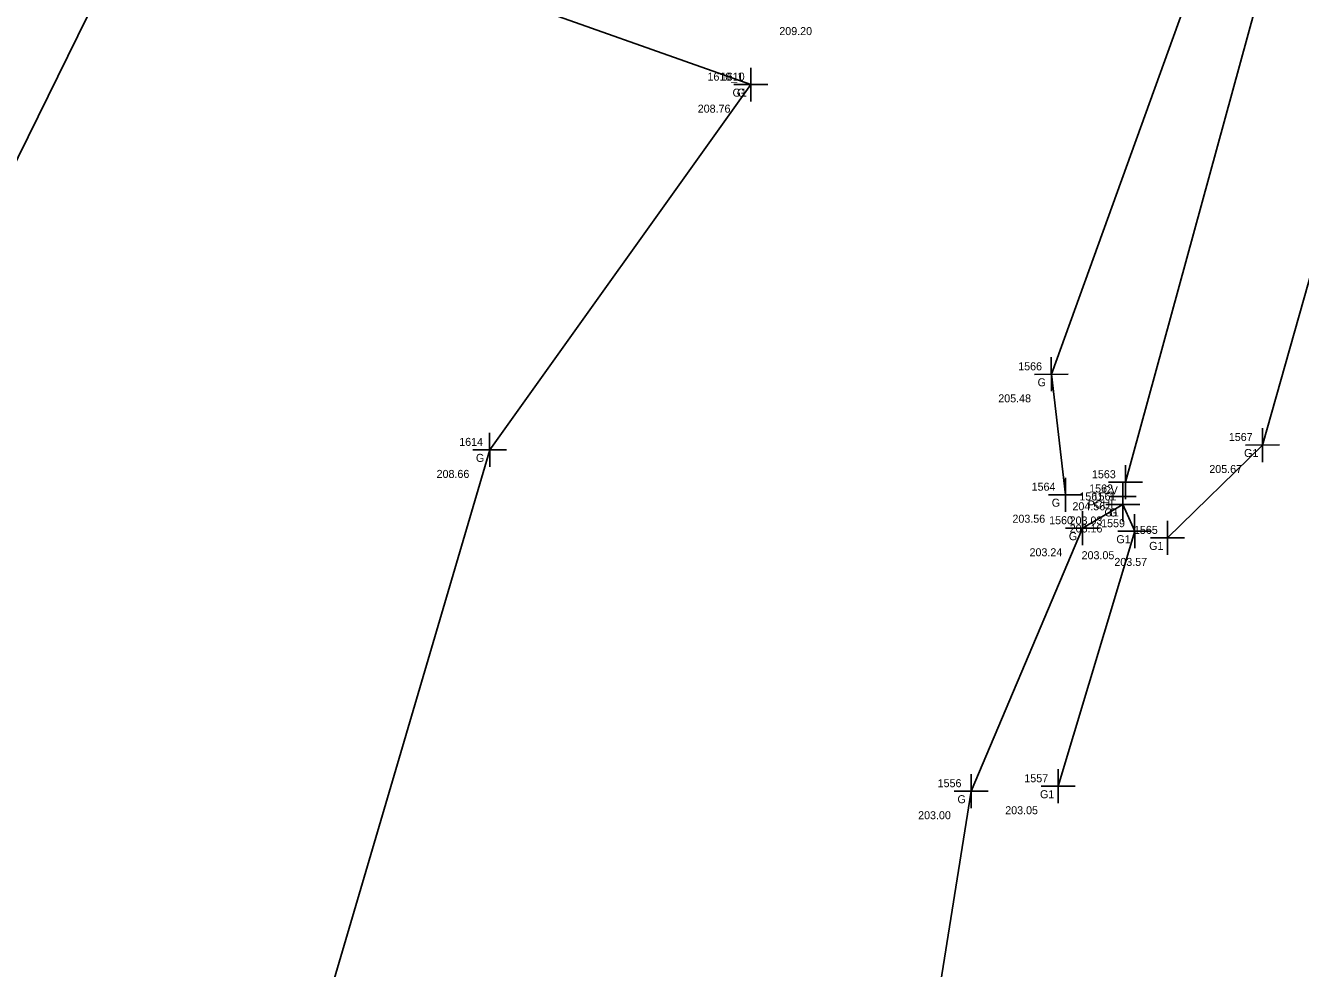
# Model space of a CAD drawing. Extents: x 1158983 to 1160032, y 610902 to 611573.
# Drawn here: x 1159316.41 to 1159364.21, y 611195.03 to 611230.37 of the extents above; entities that cross this region are included whole.
import ezdxf

# ---------------------------------------------------------------- set-up
doc = ezdxf.new("R2010")
doc.units = 0
for name, color, linetype in [('Default', 7, 'Continuous'), ('S_Drainage_Culvert_Top', 7, 'Continuous'), ('S_Drainage_Invert', 7, 'Continuous'), ('S_Field_Code', 7, 'Continuous'), ('S_Ground_Elevation', 7, 'Continuous'), ('S_Point_Elevation', 7, 'Continuous'), ('S_Point_Name', 7, 'Continuous'), ('S_Survey_Shot', 7, 'Continuous')]:
    doc.layers.add(name, color=color, linetype=linetype)

msp = doc.modelspace()

# ---------------------------------------------------------------- linework, layer by layer
at = {"layer": 'Default'}
msp.add_line((1159357.543, 611212.718), (1159357.543, 611212.718), dxfattribs=at)
at = {"layer": 'S_Drainage_Culvert_Top'}
msp.add_lwpolyline([(1159357.648, 611213.251), (1159368.247, 611251.957)], dxfattribs=at)
at = {"layer": 'S_Drainage_Invert'}
for p, q in [((1159357.543, 611213.218), (1159357.543, 611212.218)), ((1159357.043, 611212.718), (1159358.043, 611212.718))]:
    msp.add_line(p, q, dxfattribs=at)
at = {"layer": 'S_Ground_Elevation'}
for points in [[(1159355.399, 611212.784), (1159354.868, 611217.296), (1159362.619, 611238.747), (1159363.344, 611248.476), (1159364.893, 611252.092), (1159367.286, 611253.012), (1159367.04, 611258.265), (1159369.176, 611279.512)], [(1159359.22, 611211.166), (1159362.779, 611214.646), (1159369.471, 611238.288), (1159371.639, 611247.54), (1159371.624, 611251.498), (1159369.477, 611252.693), (1159372.225, 611257.365), (1159373.898, 611277.257)], [(1159343.602, 611228.151), (1159333.924, 611231.59), (1159320.612, 611234.544), (1159314.265, 611221.651), (1159310.207, 611192.625), (1159301.313, 611165.491), (1159294.216, 611125.97), (1159281.365, 611085.012)], [(1159343.602, 611228.151), (1159333.813, 611214.463), (1159327.549, 611193.141), (1159320.093, 611162.672), (1159311.847, 611125.314), (1159302.792, 611085.335), (1159282.623, 611040.075), (1159275.499, 611004.928), (1159281.6, 610988.313)], [(1159311.353, 611030.991), (1159320.755, 611050.625), (1159326.586, 611072.012), (1159334.597, 611111.75), (1159339.581, 611147.922), (1159349.474, 611186.733), (1159351.864, 611201.672), (1159356.04, 611211.527), (1159357.544, 611212.419)], [(1159355.129, 611201.859), (1159357.992, 611211.416), (1159357.544, 611212.419)]]:
    msp.add_lwpolyline(points, dxfattribs=at)
at = {"layer": 'S_Survey_Shot'}
for p, q in [((1159343.603, 611227.515), (1159343.601, 611228.787)), ((1159343.603, 611227.515), (1159343.601, 611228.787)), ((1159342.966, 611228.15), (1159344.238, 611228.152)), ((1159342.966, 611228.15), (1159344.238, 611228.152)), ((1159343.602, 611228.151), (1159343.602, 611228.151)), ((1159343.602, 611228.151), (1159343.602, 611228.151)), ((1159354.869, 611216.659), (1159354.867, 611217.932)), ((1159354.232, 611217.294), (1159355.504, 611217.297)), ((1159354.868, 611217.296), (1159354.868, 611217.296)), ((1159333.814, 611213.826), (1159333.811, 611215.099)), ((1159362.781, 611214.009), (1159362.778, 611215.282)), ((1159362.143, 611214.644), (1159363.416, 611214.647)), ((1159362.779, 611214.646), (1159362.779, 611214.646)), ((1159333.177, 611214.461), (1159334.449, 611214.464)), ((1159333.813, 611214.463), (1159333.813, 611214.463)), ((1159357.649, 611212.615), (1159357.647, 611213.887)), ((1159355.401, 611212.147), (1159355.398, 611213.42)), ((1159357.012, 611213.25), (1159358.284, 611213.252)), ((1159357.648, 611213.251), (1159357.648, 611213.251)), ((1159354.763, 611212.782), (1159356.036, 611212.785)), ((1159355.399, 611212.784), (1159355.399, 611212.784)), ((1159357.545, 611211.783), (1159357.542, 611213.056)), ((1159357.545, 611211.783), (1159357.542, 611213.056)), ((1159356.907, 611212.418), (1159358.18, 611212.421)), ((1159356.907, 611212.418), (1159358.18, 611212.421)), ((1159357.544, 611212.419), (1159357.544, 611212.419)), ((1159357.544, 611212.419), (1159357.544, 611212.419)), ((1159356.041, 611210.891), (1159356.039, 611212.163)), ((1159357.994, 611210.78), (1159357.991, 611212.053)), ((1159359.222, 611210.529), (1159359.219, 611211.802)), ((1159355.404, 611211.526), (1159356.676, 611211.528)), ((1159356.04, 611211.527), (1159356.04, 611211.527)), ((1159357.356, 611211.415), (1159358.628, 611211.418)), ((1159357.992, 611211.416), (1159357.992, 611211.416)), ((1159358.584, 611211.164), (1159359.857, 611211.167)), ((1159359.22, 611211.166), (1159359.22, 611211.166)), ((1159351.865, 611201.036), (1159351.862, 611202.308)), ((1159355.13, 611201.223), (1159355.128, 611202.495)), ((1159354.493, 611201.858), (1159355.765, 611201.86)), ((1159355.129, 611201.859), (1159355.129, 611201.859)), ((1159351.227, 611201.671), (1159352.5, 611201.673)), ((1159351.864, 611201.672), (1159351.864, 611201.672))]:
    msp.add_line(p, q, dxfattribs=at)

# ---------------------------------------------------------------- texts
at = {"layer": 'S_Field_Code'}
for s, p in [('G1', (1159342.917, 611227.701)), ('G', (1159343.087, 611227.701)), ('G', (1159354.353, 611216.846)), ('G', (1159333.298, 611214.013)), ('G1', (1159362.094, 611214.196)), ('CV', (1159356.805, 611212.801)), ('G', (1159354.884, 611212.334)), ('PCUI', (1159356.229, 611212.268)), ('G1', (1159356.859, 611211.969)), ('G', (1159357.029, 611211.969)), ('G', (1159355.525, 611211.077)), ('G1', (1159357.307, 611210.966)), ('G1', (1159358.535, 611210.715)), ('G1', (1159354.444, 611201.409)), ('G', (1159351.349, 611201.222))]:
    msp.add_text(s, height=0.3, dxfattribs=at).set_placement(p)
at = {"layer": 'S_Point_Elevation'}
for s, p in [('209.20', (1159344.671, 611230.008)), ('208.76', (1159341.613, 611227.101)), ('208.76', (1159341.613, 611227.101)), ('205.48', (1159352.879, 611216.246)), ('208.66', (1159331.824, 611213.413)), ('205.67', (1159360.79, 611213.596)), ('204.56', (1159355.659, 611212.201)), ('203.56', (1159353.41, 611211.734)), ('203.03', (1159355.554, 611211.668)), ('203.16', (1159355.555, 611211.369)), ('203.16', (1159355.555, 611211.369)), ('203.24', (1159354.051, 611210.477)), ('203.05', (1159356.003, 611210.366)), ('203.57', (1159357.231, 611210.115)), ('203.00', (1159349.875, 611200.622)), ('203.05', (1159353.14, 611200.809))]:
    msp.add_text(s, height=0.3, dxfattribs=at).set_placement(p)
at = {"layer": 'S_Point_Name'}
for s, p in [('1610_1', (1159341.979, 611228.301)), ('1610', (1159342.478, 611228.301)), ('1566', (1159353.626, 611217.446)), ('1567', (1159361.521, 611214.796)), ('1614', (1159332.672, 611214.613)), ('1563', (1159356.391, 611213.401)), ('1564', (1159354.129, 611212.934)), ('1561_1', (1159355.919, 611212.569)), ('1562', (1159356.286, 611212.868)), ('1561', (1159356.417, 611212.569)), ('1560', (1159354.786, 611211.677)), ('1559', (1159356.736, 611211.566)), ('1565', (1159357.964, 611211.315)), ('1557', (1159353.856, 611202.009)), ('1556', (1159350.607, 611201.822))]:
    msp.add_text(s, height=0.3, dxfattribs=at).set_placement(p)

doc.saveas('drawing.dxf')
